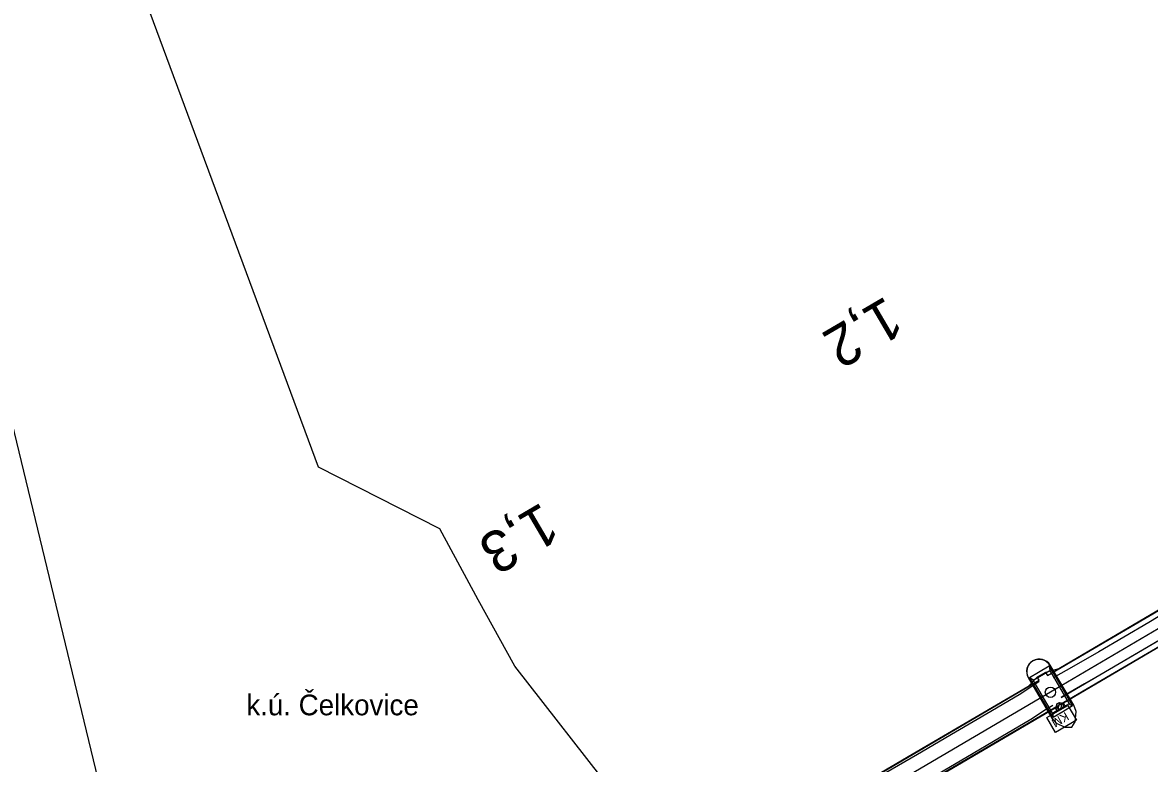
# Model space of a CAD drawing. Extents: x -738085 to -734426, y -1122197 to -1119748.
# Drawn here: x -735333 to -735169.9, y -1120297.8 to -1120190.5 of the extents above; entities that cross this region are included whole.
import ezdxf

# ---------------------------------------------------------------- set-up
doc = ezdxf.new("R2010")
doc.units = 0
for name, color, linetype in [('Polygon ku', 7, 'Continuous'), ('Vrstva 1', 7, 'Continuous'), ('Vrstva 11', 7, 'Continuous'), ('Vrstva 17', 7, 'Continuous'), ('Vrstva 18', 7, 'Continuous'), ('Vrstva 36', 7, 'Continuous'), ('Vrstva 63', 7, 'Continuous'), ('Vrstva 7', 7, 'Continuous')]:
    doc.layers.add(name, color=color, linetype=linetype)

msp = doc.modelspace()

# ---------------------------------------------------------------- linework, layer by layer
at = {"layer": 'Polygon ku'}
for p, q in [((-735272.61, -1120263.87), (-735290.18, -1120254.92)), ((-735272.61, -1120263.87), (-735290.18, -1120254.92)), ((-735267.06, -1120274.13), (-735272.61, -1120263.87)), ((-735267.06, -1120274.13), (-735272.61, -1120263.87))]:
    msp.add_line(p, q, dxfattribs=at)
for points in [[(-735290.18, -1120254.92), (-735317.57, -1120180.85), (-735339.79, -1120142.5), (-735361.49, -1120104.8), (-735379.62, -1120073.45), (-735392.28, -1120051.31)], [(-735290.18, -1120254.92), (-735317.57, -1120180.85), (-735339.79, -1120142.5), (-735361.49, -1120104.8), (-735379.62, -1120073.45), (-735392.28, -1120051.31)], [(-735247.23, -1120302.41), (-735261.74, -1120283.75), (-735267.06, -1120274.13)], [(-735247.23, -1120302.41), (-735261.74, -1120283.75), (-735267.06, -1120274.13)]]:
    msp.add_lwpolyline(points, dxfattribs=at)
at = {"layer": 'Vrstva 1'}
msp.add_lwpolyline([(-734541.63, -1119996.45), (-735348.44, -1120191.3), (-735283.42, -1120460.56), (-734476.61, -1120265.71)], close=True, dxfattribs=at)
msp.add_lwpolyline([(-735048.63, -1120207.9), (-735071.26, -1120221.19), (-735095.02, -1120235.15), (-735119.18, -1120249.35), (-735123.66, -1120251.99), (-735132.32, -1120257.08), (-735139.95, -1120261.55), (-735146.73, -1120265.54), (-735150.83, -1120267.95), (-735166.13, -1120276.92), (-735184.2, -1120287.53), (-735210.89, -1120303.2), (-735238.62, -1120319.49), (-735239.7, -1120320.12), (-735247.26, -1120324.55), (-735256.8, -1120330.14), (-735273.62, -1120340.02), (-735285.77, -1120347.18), (-735296.08, -1120353.22), (-735304.06, -1120357.75)], dxfattribs=at)
msp.add_lwpolyline([(-735048.63, -1120207.9), (-735071.26, -1120221.19), (-735095.02, -1120235.15), (-735119.18, -1120249.35), (-735123.66, -1120251.99), (-735132.32, -1120257.08), (-735139.95, -1120261.55), (-735146.73, -1120265.54), (-735150.83, -1120267.95), (-735166.13, -1120276.92), (-735184.2, -1120287.53), (-735210.89, -1120303.2), (-735238.62, -1120319.49), (-735239.7, -1120320.12), (-735247.26, -1120324.55), (-735256.8, -1120330.14), (-735273.62, -1120340.02), (-735285.77, -1120347.18), (-735296.08, -1120353.22), (-735304.06, -1120357.75)], dxfattribs=at)
at = {"layer": 'Vrstva 11'}
for p, q in [((-735182.9, -1120289.01), (-735183.13, -1120289.91)), ((-735182.54, -1120289.11), (-735182.77, -1120290))]:
    msp.add_line(p, q, dxfattribs=at)
msp.add_circle((-735182.84, -1120289.5), 0.5, dxfattribs=at)
at = {"layer": 'Vrstva 17'}
for points in [[(-735274.55, -1120337.93), (-735238.93, -1120316.99), (-735185.86, -1120285.79), (-735186.12, -1120285.36), (-735184.9, -1120284.66), (-735184.62, -1120285.09), (-735125.12, -1120250.26)], [(-735270.78, -1120340.98), (-735236.53, -1120320.93), (-735236.28, -1120321.41), (-735234.63, -1120320.42), (-735234.9, -1120319.96), (-735231.79, -1120318.14), (-735183.52, -1120289.79), (-735183.26, -1120290.18), (-735182.05, -1120289.53), (-735182.31, -1120289.06), (-735137.96, -1120263.01), (-735122.96, -1120254.17)]]:
    msp.add_lwpolyline(points, dxfattribs=at)
at = {"layer": 'Vrstva 18'}
for p, q in [((-735184.39, -1120283.72), (-735184.29, -1120284.36)), ((-735186.71, -1120285.77), (-735187.24, -1120285.37)), ((-735184.36, -1120289.7), (-735183.87, -1120289.42)), ((-735181.49, -1120289.19), (-735180.99, -1120289.52)), ((-735183.89, -1120290.58), (-735183.81, -1120291.2))]:
    msp.add_line(p, q, dxfattribs=at)
for points in [[(-735152.51, -1120267.05), (-735155.47, -1120268.89), (-735159.09, -1120271), (-735162.78, -1120273.17), (-735166.37, -1120275.27), (-735169.95, -1120277.41), (-735173.59, -1120279.55), (-735177.2, -1120281.68), (-735180.83, -1120283.75), (-735183.82, -1120285.46)], [(-735150.71, -1120269.55), (-735150.96, -1120269.62), (-735153.89, -1120271.35), (-735157.54, -1120273.56), (-735161.24, -1120275.74), (-735164.82, -1120277.83), (-735168.41, -1120279.97), (-735172.04, -1120282.11), (-735175.65, -1120284.25), (-735179.29, -1120286.31), (-735182.28, -1120288.03), (-735182.63, -1120288.29), (-735150.71, -1120269.55)], [(-735187.39, -1120285.47), (-735184, -1120291.26), (-735183.37, -1120292.03), (-735182.05, -1120292.6), (-735181.11, -1120292.6), (-735180.62, -1120291.82), (-735180.47, -1120290.34), (-735180.84, -1120289.42), (-735184.23, -1120283.63)], [(-735187.39, -1120285.47), (-735184, -1120291.26), (-735183.37, -1120292.03), (-735182.05, -1120292.6), (-735181.11, -1120292.6), (-735180.62, -1120291.82), (-735180.47, -1120290.34), (-735180.84, -1120289.42), (-735184.23, -1120283.63)], [(-735187.24, -1120285.37), (-735185.93, -1120284.62), (-735184.39, -1120283.72), (-735180.99, -1120289.52), (-735182.39, -1120290.37), (-735183.81, -1120291.2), (-735187.24, -1120285.37)], [(-735186.71, -1120285.77), (-735184.29, -1120284.36), (-735181.49, -1120289.19), (-735183.89, -1120290.58), (-735186.71, -1120285.77)], [(-735185.83, -1120285.96), (-735188.51, -1120287.75), (-735192.85, -1120290.31), (-735197.94, -1120293.3), (-735203.43, -1120296.53), (-735208.93, -1120299.74), (-735214.35, -1120302.95), (-735219.82, -1120306.12), (-735225.02, -1120309.21), (-735230.42, -1120312.39), (-735234.67, -1120314.85), (-735238.21, -1120316.84)], [(-735184.36, -1120289.7), (-735187.03, -1120291.5), (-735191.38, -1120294.06), (-735196.46, -1120297.05), (-735201.95, -1120300.27), (-735207.27, -1120303.37), (-735212.87, -1120306.69), (-735218.34, -1120309.86), (-735223.54, -1120312.96), (-735228.94, -1120316.14), (-735233.19, -1120318.6), (-735236.74, -1120320.59)]]:
    msp.add_lwpolyline(points, dxfattribs=at)
for centre, major_axis, ratio, start_param, end_param in [((-735185.81, -1120284.56), (0.46, -1.77), 0.999997, 1.849742, 4.982781), ((-735185.76, -1120284.64), (1.48, -1.26), 0.935932, 1.304923, 4.337698)]:
    msp.add_ellipse(centre, major_axis=major_axis, ratio=ratio, start_param=start_param, end_param=end_param, dxfattribs=at)
at = {"layer": 'Vrstva 36'}
msp.add_lwpolyline([(-735123.16, -1120248.87), (-735124.8, -1120249.94), (-735135.02, -1120255.93), (-735143.96, -1120261.15), (-735182.98, -1120284.14), (-735184.9, -1120284.66), (-735186.12, -1120285.36), (-735187.5, -1120286.75), (-735204.22, -1120296.53), (-735238.82, -1120316.86), (-735255.42, -1120326.68), (-735274.83, -1120337.93), (-735276.42, -1120338.77)], dxfattribs=at)
at = {"layer": 'Vrstva 63'}
msp.add_line((-735310.08, -1120363.77), (-735121.84, -1120253.57), dxfattribs=at)
at = {"layer": 'Vrstva 7'}
msp.add_line((-735183.52, -1120289.79), (-735183.21, -1120290.33), dxfattribs=at)
msp.add_lwpolyline([(-735181.71, -1120289.44), (-735180.45, -1120291.58), (-735183.46, -1120293.35), (-735184.71, -1120291.21)], close=True, dxfattribs=at)
msp.add_circle((-735184.2, -1120287.53), 0.75, dxfattribs=at)
msp.add_circle((-735184.2, -1120287.53), 0.75, dxfattribs=at)

# ---------------------------------------------------------------- texts
at = {"layer": 'Polygon ku'}
msp.add_text('k.ú. Čelkovice', height=3, dxfattribs=at).set_placement((-735300.62, -1120290.87))
at = {"layer": 'Vrstva 7'}
for s, height, rotation, p in [('1,2', 6, 210.415, (-735207.99, -1120230.05)), ('1,2', 6, 210.415, (-735207.99, -1120230.05)), ('1,3', 6, 210.4253, (-735257.8, -1120259.91)), ('1,3', 6, 210.4253, (-735257.8, -1120259.91)), ('KM', 1.247, 210.415, (-735182.02, -1120290.34))]:
    msp.add_text(s, height=height, rotation=rotation, dxfattribs=at).set_placement(p)

doc.saveas('drawing.dxf')
